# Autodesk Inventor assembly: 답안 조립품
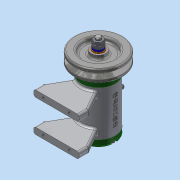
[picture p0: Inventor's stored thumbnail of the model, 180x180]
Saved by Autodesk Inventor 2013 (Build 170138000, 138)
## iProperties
Created: 2018-05
Part Number: 답안 조립품
Document SubType Name: Assembly
Designer: dgall
Author: dgall
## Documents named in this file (16)
- C:\Users\dgall\Desktop\480507V1012\답안 조립품.iam
- C:\Users\dgall\Desktop\480507V1012\본체.ipt
- C:\Users\dgall\Desktop\480507V1012\앞커버.ipt
- C:\Users\dgall\Desktop\480507V1012\뒤커버.ipt
- C:\Users\dgall\Desktop\480507V1012\오일 실 15 25 7.ipt
- C:\Users\dgall\Desktop\480507V1012\베어링 6002.ipt
- C:\Users\dgall\Desktop\480507V1012\축.ipt
- C:\Users\dgall\Desktop\480507V1012\키 3x3x12.ipt
- C:\Users\dgall\Desktop\480507V1012\V벨트풀리.ipt
- C:\Users\dgall\Desktop\480507V1012\와셔 8x17.ipt
- C:\Users\dgall\Desktop\480507V1012\스프링와셔 8.ipt
- C:\Users\dgall\Desktop\480507V1012\너트 M8.ipt
- C:\Users\dgall\Desktop\480507V1012\니플 M6x0.75.ipt
- C:\Users\dgall\Desktop\480507V1012\와셔 6x11.5.ipt
- C:\Users\dgall\Desktop\480507V1012\볼트 M6x8.ipt
- C:\Users\dgall\Desktop\480507V1012\볼트 M4x12.ipt
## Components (1 placed, 1 different names)
1. V벨트풀리:1
